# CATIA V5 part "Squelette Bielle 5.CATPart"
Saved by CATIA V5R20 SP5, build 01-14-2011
Part number: Squelette Bielle 5
Bounding box of the stored display mesh (mm): x -270 to -250, y -200 to 100, z -50 to 10
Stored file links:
  U:\CFAO\Thinkmotion\Squelette Bielle 5.CATPart
  U:\CFAO\Thinkmotion\Bras Articule.CATProduct
  U:\CFAO\Thinkmotion\Squelette general.CATPart
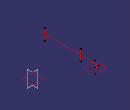
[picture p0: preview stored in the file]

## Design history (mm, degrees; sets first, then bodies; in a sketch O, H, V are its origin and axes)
Set1
  Line1: type PtPt, FirstPoint Point1, SecondPoint Point2
  Line2: type PtPt, FirstPoint Point2, SecondPoint Point3
  Line3: type PtPt, FirstPoint Point3, SecondPoint Point4
  Line4: type Normal, RefPoint Point1, RefSkin Plane2, Start -30, End 30
  Line5: type Normal, RefPoint Point3, RefSkin Plane2, Start -30, End 30
  Line6: type Normal, RefPoint Point4, RefSkin Plane2, Start -30, End 30
  Plane1: type OffsetPt, RefPlane xy-plane, RefPoint Point1
Set2
  Point1 to Point4: linked copy from another document
  Plane2: linked copy from another document
Body1 (main body)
